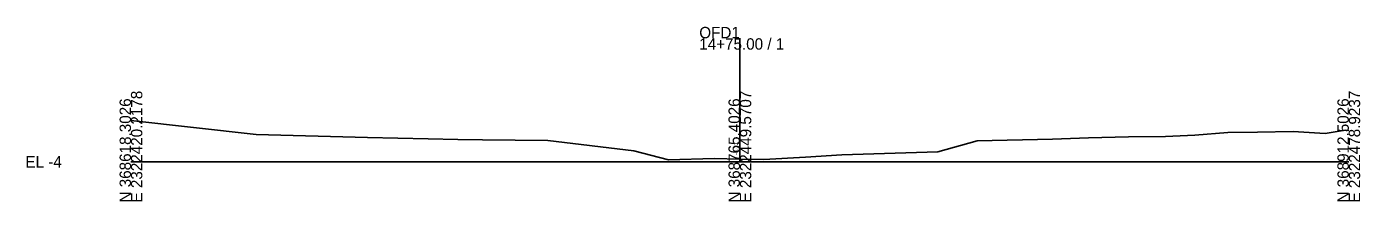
# Model space of a CAD drawing. Extents: x -26 to 303, y -10 to 14048.
# Drawn here: x -25.7 to 302.8, y 9490.3 to 9533.2 of the extents above; entities that cross this region are included whole.
import ezdxf

# ---------------------------------------------------------------- set-up
doc = ezdxf.new("R2010")
doc.units = 0
for name, color, linetype in [('RD_GPK_XS_Cell', 7, 'Continuous'), ('RD_XS_ExGround', 7, 'Continuous'), ('RD_XS_TX_Elev_EX', 7, 'Continuous')]:
    doc.layers.add(name, color=color, linetype=linetype)

msp = doc.modelspace()

# ---------------------------------------------------------------- linework, layer by layer
at = {"layer": 'RD_GPK_XS_Cell'}
for p, q in [((150, 9500), (150, 9530.38)), ((0, 9500), (150, 9500)), ((150, 9500), (300, 9500))]:
    msp.add_line(p, q, dxfattribs=at)
at = {"layer": 'RD_XS_ExGround'}
for p, q in [((0, 9510.13), (30.84, 9506.69)), ((294.18, 9506.97), (299.07, 9507.79)), ((299.07, 9507.79), (300, 9507.67)), ((30.84, 9506.69), (58.24, 9506.01)), ((58.24, 9506.01), (73.18, 9505.69)), ((73.18, 9505.69), (80.5, 9505.53)), ((80.5, 9505.53), (86.62, 9505.43)), ((86.62, 9505.43), (102.67, 9505.24)), ((102.67, 9505.24), (123.88, 9502.68)), ((198.78, 9502.43), (208.44, 9505.16)), ((208.44, 9505.16), (227.02, 9505.55)), ((227.02, 9505.55), (235.91, 9505.93)), ((235.91, 9505.93), (245.7, 9506.11)), ((245.7, 9506.11), (254.86, 9506.25)), ((254.86, 9506.25), (262.1, 9506.6)), ((262.1, 9506.6), (270.21, 9507.21)), ((270.21, 9507.21), (277.48, 9507.3)), ((277.48, 9507.3), (286.33, 9507.44)), ((286.33, 9507.44), (294.18, 9506.97)), ((123.88, 9502.68), (132.4, 9500.47)), ((155.92, 9500.56), (166.2, 9501.19)), ((166.2, 9501.19), (175.1, 9501.74)), ((175.1, 9501.74), (198.78, 9502.43)), ((132.4, 9500.47), (143.66, 9500.83)), ((143.66, 9500.83), (150, 9500.69)), ((150, 9500.69), (155.92, 9500.56))]:
    msp.add_line(p, q, dxfattribs=at)

# ---------------------------------------------------------------- texts
at = {"layer": 'RD_GPK_XS_Cell'}
for s, p in [('OFD1', (140, 9530.38)), ('14+75.00 / 1', (140, 9527.58)), ('EL -4', (-26, 9498.6))]:
    msp.add_text(s, height=2.8, dxfattribs=at).set_placement(p)
for s, p in [('N 368618.3026', (0, 9490)), ('E 2322420.2178', (2.8, 9490)), ('N 368765.4026', (150, 9490)), ('E 2322449.5707', (152.8, 9490)), ('N 368912.5026', (300, 9490)), ('E 2322478.9237', (302.8, 9490))]:
    msp.add_text(s, height=2.8, rotation=90, dxfattribs=at).set_placement(p)
at = {"layer": 'RD_XS_TX_Elev_EX'}
msp.add_text('-3.31', height=1, rotation=90, dxfattribs=at).set_placement((149.5, 9501.69))

doc.saveas('drawing.dxf')
